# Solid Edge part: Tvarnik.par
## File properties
Author: jachy
Template: iso metric part.par
Last saved by: jachy
Revision: 10
Application: Solid Edge
Username: jachy
Typ obsahu dokumentu: 0
Hustota: 0,000 kg/m^3
Přesnost: 0,990
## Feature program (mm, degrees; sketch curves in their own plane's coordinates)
body "unnamed Body 1"
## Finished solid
Body 1: solid body, 229 faces, 540 edges, 344 vertices.
  Faces by surface: spline 175, cylinder 27, plane 13, swept 8, torus 4, sphere 1, spun 1
  Edges by curve: curve on surface 443, circle 43, spline 29, line 25
Bounding box of the edges (mm; curved faces can reach further): 334.731 x 150.000 x 66.481, from (-70.5667, -58.9307, -16.7981) to (264.1638, 91.0693, 49.683).
Cylindrical faces by radius (mm): R1.0199 x1, R1.02 x3, R3.0489 x1, R3.0599 x1, R3.06 x3, R3.0601 x1, R5.1 x1, R5.5 x4, R8 x4, R8.5 x4, R10.1016 x1, R22.5074 x1, R25.4861 x1, R720.5744 x1
Toroidal faces (ring radius, tube radius in mm): R8 r0.5 x4
Spherical faces by radius (mm): R5.2026 x1
Planar faces by outward normal: +y 1, -y 1, oblique 11
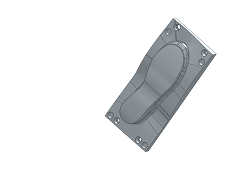
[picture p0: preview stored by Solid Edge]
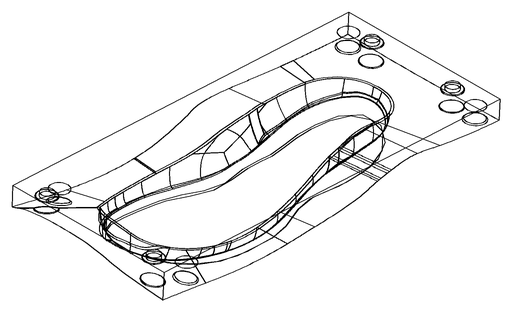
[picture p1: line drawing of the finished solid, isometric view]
